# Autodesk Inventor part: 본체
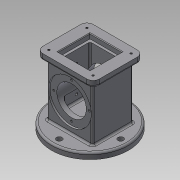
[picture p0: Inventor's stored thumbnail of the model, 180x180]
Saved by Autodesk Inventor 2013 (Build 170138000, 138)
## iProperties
Created: 2018-10
Part Number: 본체
Material: 일반
Document SubType Name: Modeling
Designer: hana-max6
Density: 1 g/cm^3
Author: hana-max6
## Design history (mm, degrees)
sketch "스케치1"
  geometry: C1 r 62.5 at (0, 0); 1 further point
  constraints: 1 centre point, 1 coincident
  dimensions: "d0" = 125 diameter of C1
extrude "돌출1" new body sketch "스케치1" distance "d2" = 10; taper "d3" = 0 deg
sketch "스케치2"
  geometry: L1 (-37, -33)-(37, -33); L2 (37, -33)-(37, 33); L3 (37, 33)-(-37, 33); L4 (-37, 33)-(-37, -33); L5 (-37, -33)-(37, 33); L6 (37, -33)-(-37, 33); C1 r 62.5 at (0, 0) reference
  constraints: 12 end point, 2 midpoint, 2 parallel, 1 horizontal, 1 perpendicular
  dimensions: "d4" = 74 distance of L3.end L2.end; "d5" = 66 distance of L2.end L1.end
extrude "돌출2" join sketch "스케치2" distance "d6" = 88; taper "d7" = 0 deg
sketch "스케치3"
  geometry: L1 (-46, -41)-(46, -41); L2 (46, -41)-(46, 41); L3 (46, 41)-(-46, 41); L4 (-46, 41)-(-46, -41); L5 (-46, -41)-(46, 41); L6 (46, -41)-(-46, 41); 1 further point
  constraints: 12 end point, 2 midpoint, 2 parallel, 1 horizontal, 1 perpendicular
  dimensions: "d8" = 92 distance of L3.end L2.end; "d9" = 82 distance of L2.end L1.end
extrude "돌출3" join sketch "스케치3" distance "d10" = 10; taper "d11" = 0 deg
sketch "스케치5"
  geometry: L1 (-33, 89)-(-30, 89); L2 (-30, 89)-(-30, 78); L3 (-30, 78)-(30, 78); L4 (30, 78)-(30, 89); L5 (30, 89)-(33, 89); L6 (-63.016, 54)-(67.581, 54); L7 (-62.5, 0)-(62.5, 0) reference; L8 (-33, 89)-(-33, 54); L9 (33, 89)-(33, 54); 3 further points
  constraints: 16 end point, 4 horizontal, 2 midpoint, 2 point on line, 2 vertical, 1 collinear, 1 vertical alignment
  dimensions: "d12" = 54 distance between parallel lines of L7 L6; "d13" = 70 diameter of L1 L6; "d14" = 48 diameter of L3 L6; "d17" = 3 distance between parallel lines of L4 L9; "d18" = 33 distance from line of point (0, 0) L9; "d20" = 66 distance between parallel lines of L9 L8
revolve "회전1" sketch "스케치5" stored, may be unused: angle "d21" = 90 deg
sketch "스케치6"
  geometry: C1 r 62.5 at (0, 0) reference; C2 r 28 at (0, 0)
  constraints: 1 centre point, 1 coincident
  dimensions: "d23" = 56 diameter of C2
extrude "돌출4" cut sketch "스케치6" distance "d25" = 18; taper "d26" = 0 deg
feature "면 기울기1" dims angle "d27" = 10 deg
fillet "모깎기1" dims "d28" = 3
fillet "모깎기2" dims "d29" = 3
sketch "스케치7"
  geometry: L1 (26, -26)-(-26, -26); L2 (-26, -26)-(-26, 26); L3 (-26, 26)-(26, 26); L4 (26, 26)-(26, -26); L5 (26, -26)-(-26, 26); L6 (-26, -26)-(26, 26); 1 further point
  constraints: 12 end point, 2 midpoint, 2 parallel, 1 horizontal, 1 perpendicular
  dimensions: "d30" = 52 distance of L2.end L3.end; "d31" = 52 distance of L1.end L2.end
extrude "돌출5" cut sketch "스케치7" distance "d32" = 8; taper "d33" = 0 deg
sketch "스케치8"
  geometry: L1 (-22, -22)-(22, -22); L2 (22, -22)-(22, 22); L3 (22, 22)-(-22, 22); L4 (-22, 22)-(-22, -22); L5 (-22, -22)-(22, 22); L6 (22, -22)-(-22, 22); 1 further point
  constraints: 12 end point, 2 midpoint, 2 parallel, 1 horizontal, 1 perpendicular
  dimensions: "d34" = 44 distance of L3.end L2.end; "d35" = 44 distance of L2.end L1.end
extrude "돌출6" cut sketch "스케치8" distance "d36" = 74; taper "d37" = 0 deg
chamfer "모따기1" distance "d38" = 1; stored, may be unused: second distance "d39" = 2, angle "d40" = 45 deg
fillet "모깎기3" dims "d41" = 3
fillet "모깎기4" dims "d42" = 3
fillet "모깎기5" dims "d43" = 10
fillet "모깎기6" dims "d44" = 3
fillet "모깎기7" dims "d45" = 3
fillet "모깎기8" dims "d46" = 3
sketch "스케치9" dims "d48" = 58
  geometry: C1 r 24 at (0, 0) reference; C2 r 35 at (0, 0) reference; 3 further points
  constraints: 2 vertical alignment, 1 coincident, 2 other
hole "구멍1" sketch "스케치9" at (0, 29) diameter "d50" = 3.242; stored, may be unused: countersink angle "d54" = 90 deg, drill point angle "d56" = 118 deg; dims "d51" = 4, "d52" = 4, "d53" = 2, "d55" = 6
sketch "스케치10"
  geometry: A1 r 10 centre (-36, 31) between (-36, 41) and (-46, 31) reference; A2 r 10 centre (-36, -31) between (-46, -31) and (-36, -41) reference; A3 r 10 centre (36, -31) between (36, -41) and (46, -31) reference; A4 r 10 centre (36, 31) between (46, 31) and (36, 41) reference; 1 further point
hole "구멍2" sketch "스케치10" at (-36, -31), (36, -31), (36, 31), (-36, 31) diameter "d60" = 3.242; stored, may be unused: countersink angle "d64" = 90 deg, drill point angle "d66" = 118 deg; dims "d61" = 4, "d62" = 4, "d63" = 2, "d65" = 6
sketch "스케치11" dims "d68" = 100
  geometry: C1 r 59.5 at (0, 0) reference; 2 further points
  constraints: 2 vertical alignment, 1 coincident, 2 other
hole "구멍3" sketch "스케치11" at (0, 50) diameter "d70" = 9; stored, may be unused: countersink angle "d74" = 90 deg, drill point angle "d76" = 118 deg; dims "d71" = 4, "d72" = 4, "d73" = 2, "d75" = 6
sketch "스케치12"
  geometry: L1 (0, 60)-(0, 0) reference; L2 (-82, 0)-(-82, 60) reference; L3 (-82, 30)-(0, 30); L4 (-95, 92.5)-(-95, -32.5) reference; 3 further points
  constraints: 2 end point, 2 midpoint, 2 point on line
  dimensions: "d80" = 37 distance from line of L4 point (-58, 30); "d81" = 43 distance of point (-58, 30) point (-15, 30)
hole "구멍4" sketch "스케치12" at (-58, 30), (-15, 30) diameter "d82" = 4.134; stored, may be unused: countersink angle "d86" = 90 deg, drill point angle "d88" = 118 deg; dims "d83" = 4, "d84" = 4, "d85" = 2, "d87" = 50
sketch "스케치13"
  geometry: L1 (72, 0)-(0, 0) reference; L2 (82, 0)-(82, 7) reference; 2 further points
  constraints: 1 other
  dimensions: "d89" = 4 distance from line of point (36, 4) L1; "d90" = 46 distance from line of L2 point (36, 4)
feature "엠보싱1" sketch "스케치13" dims "d3" = 0, "d11" = 0, "d91" = 0.5, "d92" = 0
node "솔리드1"
pattern_circular "원형 패턴1" dims angle "d58" = 360 deg
mirror "대칭1"
pattern_circular "원형 패턴2" dims angle "d78" = 360 deg
